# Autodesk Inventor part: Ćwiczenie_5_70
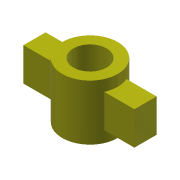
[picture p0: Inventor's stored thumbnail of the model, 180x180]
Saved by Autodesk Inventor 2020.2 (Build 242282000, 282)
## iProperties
Created: 2005-08
Part Number: Ćwiczenie_5_70
Document SubType Name: Modeling
Designer: F.Stasiak
Manufacturer: Standard
Standards Organization: Custom
Density: 1 g/cm^3
Material: Ogólny
Appearance: Żółta
Manager: www.cadconsulting.pl
Company: Fabian Stasiak CAD Consulting
Author: F.Stasiak
Subject: Zbiór ćwiczeń. Autodesk Inventor 2020. Kurs podstawowy
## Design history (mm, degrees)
sketch "Szkic1"
  geometry: L1 (0, 0)-(100, 0); L2 (100, 0)-(100, 20); L3 (100, 20)-(0, 20); L4 (0, 20)-(0, 0); L5 (0, 10)-(100, 10); C1 r 25 at (50, 10)
  constraints: 10 end point, 3 midpoint, 2 parallel, 1 centre point, 1 horizontal, 1 perpendicular
  dimensions: "d0" = 100 distance of L1.start L1.end; "d1" = 20 distance of L3.end L1.start; "d2" = 50 diameter of C1
extrude "Wyciągnięcie proste1" new body sketch "Szkic1" stored distance "d3" = 30; taper "d4" = 0 deg
extrude "Wyciągnięcie proste2" join sketch "Szkic1" stored distance "d5" = 50; taper "d6" = 0 deg
sketch "Szkic2"
  geometry: C1 r 25 at (0, 0) reference; C2 r 15 at (0, 0)
  constraints: 1 centre point
  dimensions: "d7" = 30 diameter of C2
extrude "Wyciągnięcie proste3" cut sketch "Szkic2" extent not by distance; stored distance "d8" = 50; taper "d9" = 0 deg
node "Bryła1"
node "Korpusy bryłowe"
node "Korpusy powierzchniowe"
